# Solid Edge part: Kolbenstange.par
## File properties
Username: ahadarics
Dokumentum tartalom típus: 0
Author: ahadarics
Last saved by: ahadarics
Revision: 87
Sűrűség: 0,000 kg/m^3
Pontosság: 0,990
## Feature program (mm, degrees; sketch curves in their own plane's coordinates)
base feature "unnamed BaseFeature 1"
thread "unnamed Thread 1"
chamfer "Letörés_1" setback 0.7
sketch for "Kihúzás_1" plane through (54.25, 0, 0) normal (1, 0, 0) x-axis (0, -1, 0)
  circle centre (0, 0) radius 10
extrude "Kihúzás_1" add finite 26.5 along -normal
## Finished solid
Body 1: solid body, 13 faces, 23 edges, 12 vertices.
  Faces by surface: plane 9, cylinder 3, cone 1
  Edges by curve: line 12, circle 11
Bounding box of the edges (mm): 588.000 x 20.000 x 20.000, from (-533.75, -10, -10) to (54.25, 10, 10).
Cylindrical faces by radius (mm): R4 x2, R10 x1
Conical faces (half-angle, radius in mm at the cone's reference point): 45 deg R3.3 x1
Planar faces by outward normal: +x 3, +z 1, -x 4, -z 1
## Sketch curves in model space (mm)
circle centre (54.25, 0, 0) radius 10
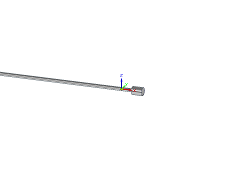
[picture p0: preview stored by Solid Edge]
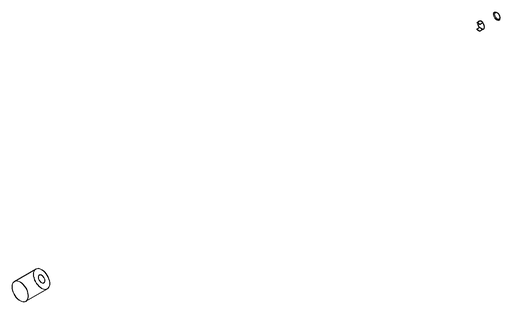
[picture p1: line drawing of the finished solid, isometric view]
